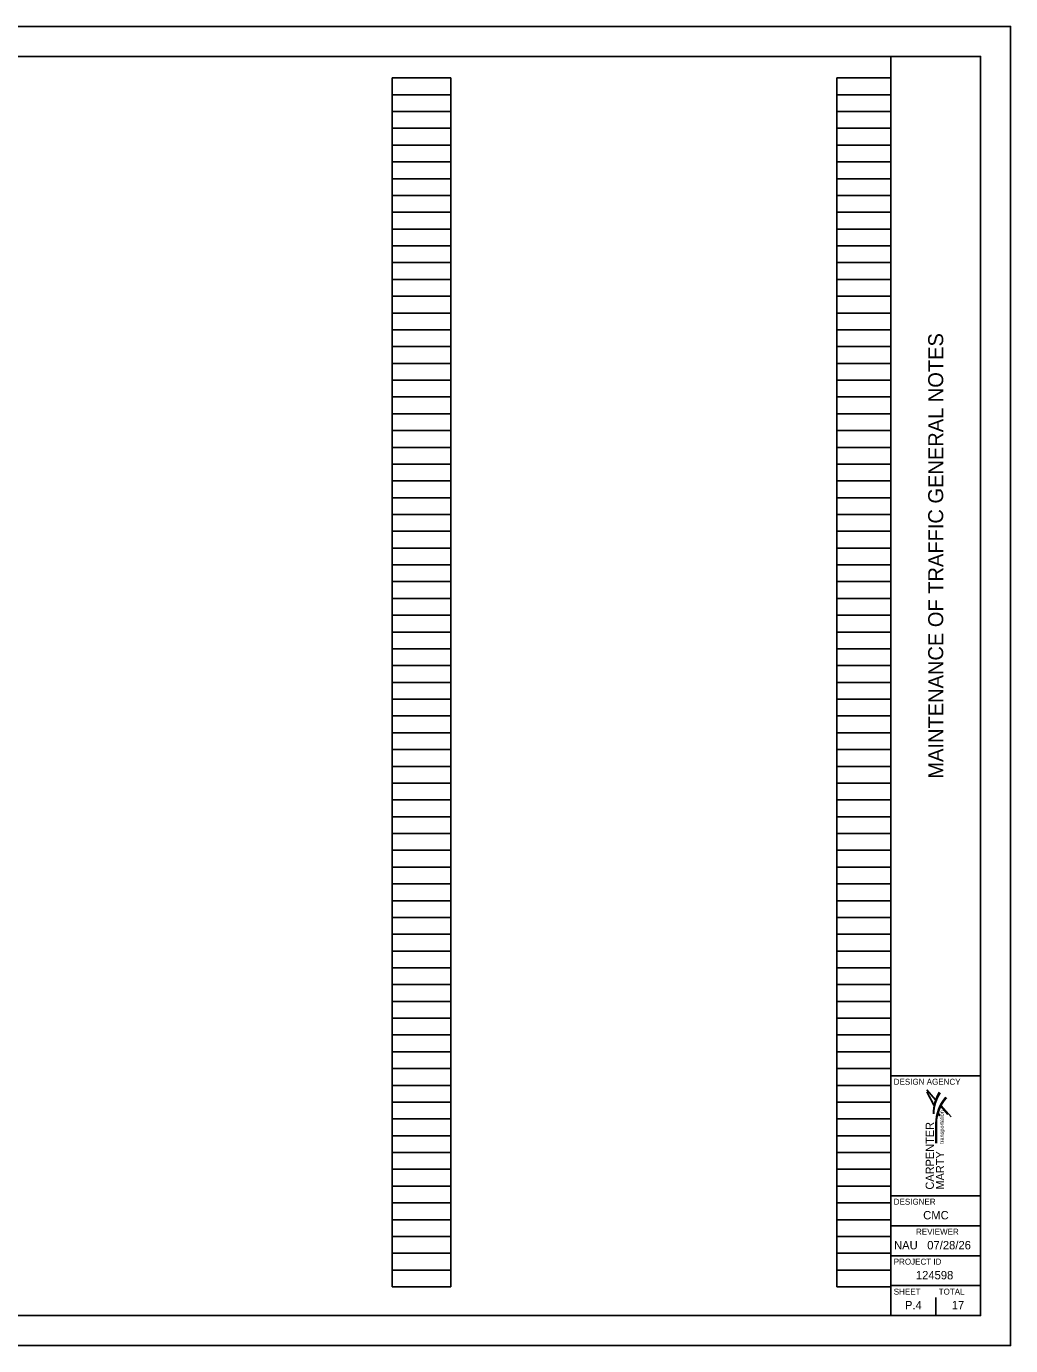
# Model space of a CAD drawing. Extents: x 0 to 34, y 0 to 22.
# Drawn here: x 17.58 to 34, y 0 to 22 of the extents above; entities that cross this region are included whole.
import ezdxf

# ---------------------------------------------------------------- set-up
doc = ezdxf.new("R2010")
doc.units = 0
for name, color, linetype in [('SH_Border', 7, 'Continuous'), ('SH_Cut_Line', 7, 'Continuous'), ('SH_Data', 7, 'Continuous'), ('SH_Text', 7, 'Continuous')]:
    doc.layers.add(name, color=color, linetype=linetype)

msp = doc.modelspace()

# ---------------------------------------------------------------- linework, layer by layer
at = {"layer": 'SH_Border'}
for p, q in [((32, 0.5), (32, 21.5)), ((32, 4.5), (33.5, 4.5)), ((32, 2.5), (33.5, 2.5)), ((32, 2), (33.5, 2)), ((32, 1.5), (33.5, 1.5)), ((32, 1), (33.5, 1))]:
    msp.add_line(p, q, dxfattribs=at)
msp.add_lwpolyline([(1.5, 21.5), (33.5, 21.5), (33.5, 0.5), (1.5, 0.5)], close=True, dxfattribs=at)
at = {"layer": 'SH_Cut_Line'}
msp.add_lwpolyline([(0, 0), (34, 0), (34, 22), (0, 22)], close=True, dxfattribs=at)
at = {"layer": 'SH_Data'}
for p, q in [((23.68, 0.98), (23.68, 21.14)), ((23.68, 21.14), (24.66, 21.14)), ((24.66, 0.98), (24.66, 21.14)), ((31.1, 0.98), (31.1, 21.14)), ((31.1, 21.14), (32, 21.14)), ((32, 0.98), (32, 21.14)), ((23.68, 20.86), (24.66, 20.86)), ((31.1, 20.86), (32, 20.86)), ((23.68, 20.58), (24.66, 20.58)), ((31.1, 20.58), (32, 20.58)), ((23.68, 20.3), (24.66, 20.3)), ((31.1, 20.3), (32, 20.3)), ((23.68, 20.02), (24.66, 20.02)), ((31.1, 20.02), (32, 20.02)), ((23.68, 19.74), (24.66, 19.74)), ((31.1, 19.74), (32, 19.74)), ((23.68, 19.46), (24.66, 19.46)), ((31.1, 19.46), (32, 19.46)), ((23.68, 19.18), (24.66, 19.18)), ((31.1, 19.18), (32, 19.18)), ((23.68, 18.9), (24.66, 18.9)), ((31.1, 18.9), (32, 18.9)), ((23.68, 18.62), (24.66, 18.62)), ((31.1, 18.62), (32, 18.62)), ((23.68, 18.34), (24.66, 18.34)), ((31.1, 18.34), (32, 18.34)), ((23.68, 18.06), (24.66, 18.06)), ((31.1, 18.06), (32, 18.06)), ((23.68, 17.78), (24.66, 17.78)), ((31.1, 17.78), (32, 17.78)), ((23.68, 17.5), (24.66, 17.5)), ((31.1, 17.5), (32, 17.5)), ((23.68, 17.22), (24.66, 17.22)), ((31.1, 17.22), (32, 17.22)), ((23.68, 16.94), (24.66, 16.94)), ((31.1, 16.94), (32, 16.94)), ((23.68, 16.66), (24.66, 16.66)), ((31.1, 16.66), (32, 16.66)), ((23.68, 16.38), (24.66, 16.38)), ((31.1, 16.38), (32, 16.38)), ((23.68, 16.1), (24.66, 16.1)), ((31.1, 16.1), (32, 16.1)), ((23.68, 15.82), (24.66, 15.82)), ((31.1, 15.82), (32, 15.82)), ((23.68, 15.54), (24.66, 15.54)), ((31.1, 15.54), (32, 15.54)), ((23.68, 15.26), (24.66, 15.26)), ((31.1, 15.26), (32, 15.26)), ((23.68, 14.98), (24.66, 14.98)), ((31.1, 14.98), (32, 14.98)), ((23.68, 14.7), (24.66, 14.7)), ((31.1, 14.7), (32, 14.7)), ((23.68, 14.42), (24.66, 14.42)), ((31.1, 14.42), (32, 14.42)), ((23.68, 14.14), (24.66, 14.14)), ((31.1, 14.14), (32, 14.14)), ((23.68, 13.86), (24.66, 13.86)), ((31.1, 13.86), (32, 13.86)), ((23.68, 13.58), (24.66, 13.58)), ((31.1, 13.58), (32, 13.58)), ((23.68, 13.3), (24.66, 13.3)), ((31.1, 13.3), (32, 13.3)), ((23.68, 13.02), (24.66, 13.02)), ((31.1, 13.02), (32, 13.02)), ((23.68, 12.74), (24.66, 12.74)), ((31.1, 12.74), (32, 12.74)), ((23.68, 12.46), (24.66, 12.46)), ((31.1, 12.46), (32, 12.46)), ((23.68, 12.18), (24.66, 12.18)), ((31.1, 12.18), (32, 12.18)), ((23.68, 11.9), (24.66, 11.9)), ((31.1, 11.9), (32, 11.9)), ((23.68, 11.62), (24.66, 11.62)), ((31.1, 11.62), (32, 11.62)), ((23.68, 11.34), (24.66, 11.34)), ((31.1, 11.34), (32, 11.34)), ((23.68, 11.06), (24.66, 11.06)), ((31.1, 11.06), (32, 11.06)), ((23.68, 10.78), (24.66, 10.78)), ((31.1, 10.78), (32, 10.78)), ((23.68, 10.5), (24.66, 10.5)), ((31.1, 10.5), (32, 10.5)), ((23.68, 10.22), (24.66, 10.22)), ((31.1, 10.22), (32, 10.22)), ((23.68, 9.94), (24.66, 9.94)), ((31.1, 9.94), (32, 9.94)), ((23.68, 9.66), (24.66, 9.66)), ((31.1, 9.66), (32, 9.66)), ((23.68, 9.38), (24.66, 9.38)), ((31.1, 9.38), (32, 9.38)), ((23.68, 9.1), (24.66, 9.1)), ((31.1, 9.1), (32, 9.1)), ((23.68, 8.82), (24.66, 8.82)), ((31.1, 8.82), (32, 8.82)), ((23.68, 8.54), (24.66, 8.54)), ((31.1, 8.54), (32, 8.54)), ((23.68, 8.26), (24.66, 8.26)), ((31.1, 8.26), (32, 8.26)), ((23.68, 7.98), (24.66, 7.98)), ((31.1, 7.98), (32, 7.98)), ((23.68, 7.7), (24.66, 7.7)), ((31.1, 7.7), (32, 7.7)), ((23.68, 7.42), (24.66, 7.42)), ((31.1, 7.42), (32, 7.42)), ((23.68, 7.14), (24.66, 7.14)), ((31.1, 7.14), (32, 7.14)), ((23.68, 6.86), (24.66, 6.86)), ((31.1, 6.86), (32, 6.86)), ((23.68, 6.58), (24.66, 6.58)), ((31.1, 6.58), (32, 6.58)), ((23.68, 6.3), (24.66, 6.3)), ((31.1, 6.3), (32, 6.3)), ((23.68, 6.02), (24.66, 6.02)), ((31.1, 6.02), (32, 6.02)), ((23.68, 5.74), (24.66, 5.74)), ((31.1, 5.74), (32, 5.74)), ((23.68, 5.46), (24.66, 5.46)), ((31.1, 5.46), (32, 5.46)), ((23.68, 5.18), (24.66, 5.18)), ((31.1, 5.18), (32, 5.18)), ((23.68, 4.9), (24.66, 4.9)), ((31.1, 4.9), (32, 4.9)), ((23.68, 4.62), (24.66, 4.62)), ((31.1, 4.62), (32, 4.62)), ((23.68, 4.34), (24.66, 4.34)), ((31.1, 4.34), (32, 4.34)), ((23.68, 4.06), (24.66, 4.06)), ((31.1, 4.06), (32, 4.06)), ((23.68, 3.78), (24.66, 3.78)), ((31.1, 3.78), (32, 3.78)), ((23.68, 3.5), (24.66, 3.5)), ((31.1, 3.5), (32, 3.5)), ((32.75, 3.5), (32.75, 3.5)), ((23.68, 3.22), (24.66, 3.22)), ((31.1, 3.22), (32, 3.22)), ((23.68, 2.94), (24.66, 2.94)), ((31.1, 2.94), (32, 2.94)), ((23.68, 2.66), (24.66, 2.66)), ((31.1, 2.66), (32, 2.66)), ((23.68, 2.38), (24.66, 2.38)), ((31.1, 2.38), (32, 2.38)), ((23.68, 2.1), (24.66, 2.1)), ((31.1, 2.1), (32, 2.1)), ((23.68, 1.82), (24.66, 1.82)), ((31.1, 1.82), (32, 1.82)), ((23.68, 1.54), (24.66, 1.54)), ((31.1, 1.54), (32, 1.54)), ((23.68, 1.26), (24.66, 1.26)), ((31.1, 1.26), (32, 1.26)), ((23.68, 0.98), (24.66, 0.98)), ((31.1, 0.98), (32, 0.98)), ((32.375, 0.675), (32.375, 0.675)), ((32.75, 0.5), (32.75, 0.8))]:
    msp.add_line(p, q, dxfattribs=at)
at = {"layer": 'SH_Text'}
for p, q in [((32.721, 4.016), (32.602, 4.232)), ((32.952, 3.853), (32.834, 3.991)), ((32.839, 4.002), (33.006, 3.816)), ((32.811, 3.84), (32.79, 3.88)), ((32.82, 3.834), (32.791, 3.886)), ((32.755, 3.378), (32.755, 3.704)), ((32.762, 3.378), (32.762, 3.704))]:
    msp.add_line(p, q, dxfattribs=at)
for points in [[(32.746, 4.104), (32.601, 4.266)], [(32.601, 4.266), (32.744, 4.098)], [(32.721, 4.016), (32.602, 4.232)], [(32.602, 4.232), (32.719, 4.011)]]:
    msp.add_lwpolyline(points, dxfattribs=at)
for centre, radius, start, end in [((33.432, 3.86), 0.721, 149.5704, 179.5529), ((33.373, 3.862), 0.654, 147.1423, 179.6525), ((33.426, 3.704), 0.671, 139.2898, 180.0106), ((33.433, 3.688), 0.672, 138.5126, 178.6075)]:
    msp.add_arc(centre, radius, start, end, dxfattribs=at)

# ---------------------------------------------------------------- texts
at = {"layer": 'SH_Data'}
msp.add_text('MAINTENANCE OF TRAFFIC GENERAL NOTES', height=0.25, rotation=90, dxfattribs=at).set_placement((32.875, 9.455))
for s, height, p in [('DESIGN AGENCY', 0.1, (32.05, 4.35)), ('DESIGNER', 0.1, (32.05, 2.35)), ('CMC', 0.14, (32.541, 2.105)), ('REVIEWER', 0.1, (32.422, 1.85)), ('NAU', 0.14, (32.055, 1.605)), ('07/28/26', 0.14, (32.609, 1.605)), ('PROJECT ID', 0.1, (32.05, 1.35)), ('124598', 0.14, (32.419, 1.105)), ('SHEET', 0.1, (32.05, 0.85)), ('TOTAL', 0.1, (32.8, 0.85)), ('P.4', 0.14, (32.237, 0.605)), ('17', 0.14, (33.018, 0.605))]:
    msp.add_text(s, height=height, dxfattribs=at).set_placement(p)
at = {"layer": 'SH_Text'}
for s, height, p in [('transportation', 0.06649, (32.885, 3.364)), ('CARPENTER ', 0.1367, (32.719, 2.602)), ('MARTY', 0.1367, (32.891, 2.602))]:
    msp.add_text(s, height=height, rotation=90, dxfattribs=at).set_placement(p)

doc.saveas('drawing.dxf')
